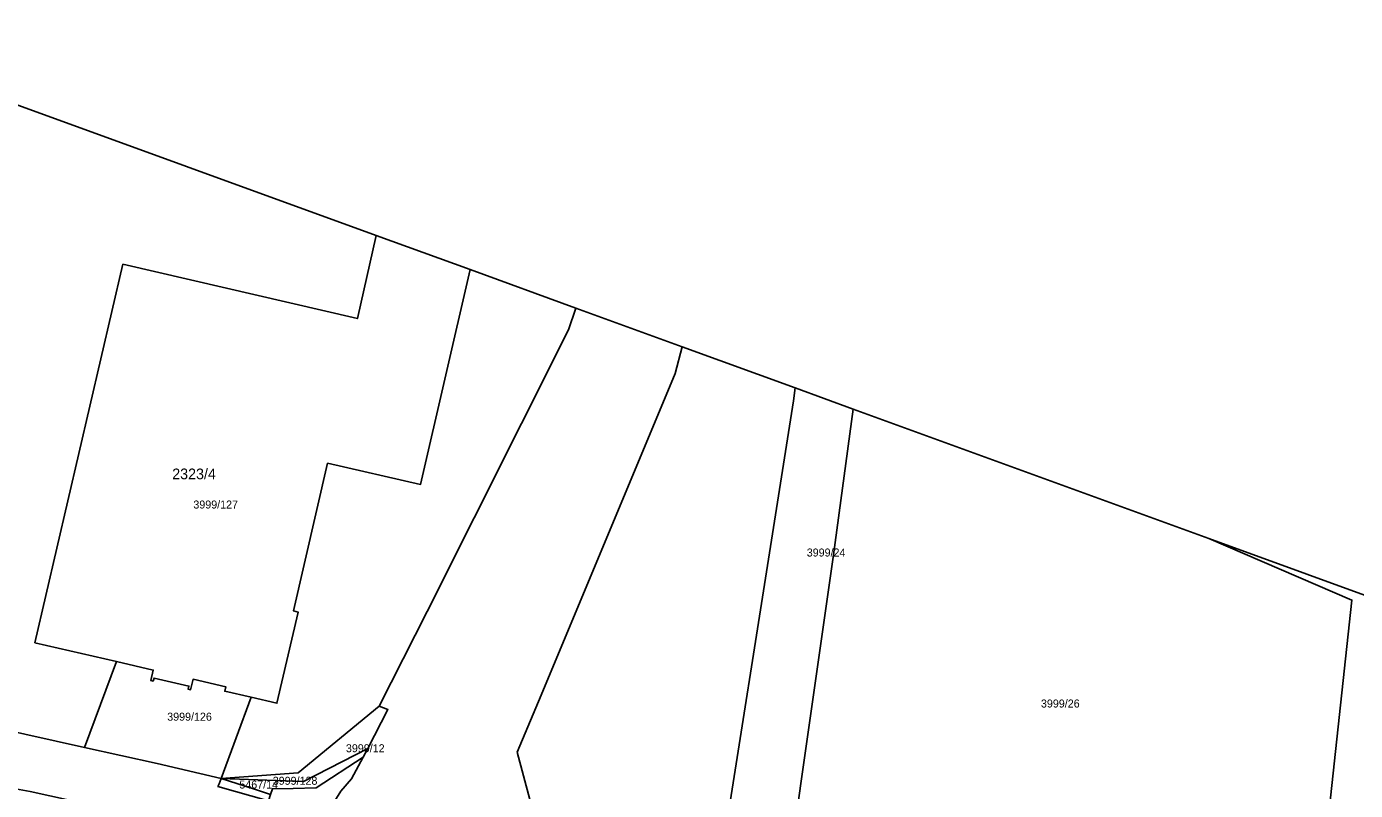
# Model space of a CAD drawing. Extents: x -570104 to -569328, y -1087857 to -1087418.
# Drawn here: x -569780.6 to -569531.5, y -1087571.3 to -1087428.2 of the extents above; entities that cross this region are included whole.
import ezdxf

# ---------------------------------------------------------------- set-up
doc = ezdxf.new("R2010")
doc.units = 0
for name, color, linetype in [('Adresní místo-text', 7, 'Continuous'), ('Parcela-polygon', 7, 'Continuous'), ('Parcela-text', 7, 'Continuous')]:
    doc.layers.add(name, color=color, linetype=linetype)

msp = doc.modelspace()

# ---------------------------------------------------------------- linework, layer by layer
at = {"layer": 'Parcela-polygon'}
for p, q in [((-569715.03, -1087467.34), (-569822.61, -1087428.2)), ((-569697.44, -1087473.74), (-569715.03, -1087467.34)), ((-569677.61, -1087480.95), (-569697.44, -1087473.74)), ((-569657.69, -1087488.2), (-569677.61, -1087480.95)), ((-569636.55, -1087495.89), (-569657.69, -1087488.2)), ((-569625.65, -1087499.86), (-569636.55, -1087495.89)), ((-569559, -1087524.1), (-569625.65, -1087499.86))]:
    msp.add_line(p, q, dxfattribs=at)
for points in [[(-569822.61, -1087428.2), (-569822.82, -1087428.95), (-569824.63, -1087435.4), (-569829.67, -1087453.35), (-569845.61, -1087508.96), (-569852.89, -1087536.4), (-569837.58, -1087552.32), (-569829.74, -1087553.51), (-569813.25, -1087555.99), (-569786.28, -1087559.57), (-569769.73, -1087563.25), (-569763.69, -1087547.17), (-569779, -1087543.64), (-569762.52, -1087472.72), (-569718.57, -1087482.91), (-569715.03, -1087467.34)], [(-569715.03, -1087467.34), (-569718.57, -1087482.91), (-569762.52, -1087472.72), (-569779, -1087543.64), (-569763.69, -1087547.17), (-569756.82, -1087548.76), (-569757.27, -1087550.72), (-569756.86, -1087550.83), (-569756.68, -1087550.26), (-569750.14, -1087551.74), (-569750.26, -1087552.35), (-569749.82, -1087552.43), (-569749.36, -1087550.47), (-569743.24, -1087551.87), (-569743.42, -1087552.72), (-569738.49, -1087553.86), (-569733.65, -1087554.97), (-569729.68, -1087537.88), (-569730.53, -1087537.68), (-569724.17, -1087510.02), (-569706.74, -1087513.97), (-569697.44, -1087473.74)], [(-569697.44, -1087473.74), (-569706.74, -1087513.97), (-569724.17, -1087510.02), (-569730.53, -1087537.68), (-569729.68, -1087537.88), (-569733.65, -1087554.97), (-569738.49, -1087553.86), (-569744.09, -1087569.05), (-569729.67, -1087568), (-569714.5, -1087555.5), (-569705.5, -1087537.75), (-569679, -1087485), (-569677.61, -1087480.95)], [(-569677.61, -1087480.95), (-569679, -1087485), (-569705.5, -1087537.75), (-569714.5, -1087555.5), (-569712.84, -1087556.16), (-569716.64, -1087563.44), (-569717.5, -1087565.1), (-569719.66, -1087569.11), (-569721.65, -1087571.42)], [(-569657.69, -1087488.2), (-569659, -1087493.2), (-569684.16, -1087553.44), (-569688.63, -1087564.12), (-569686.23, -1087572.99), (-569680.91, -1087587.07), (-569672.82, -1087596.37), (-569655.79, -1087606.73), (-569655.45, -1087604.65), (-569653.75, -1087605.49), (-569636.87, -1087498.32), (-569636.55, -1087495.89)], [(-569686.23, -1087572.99), (-569688.63, -1087564.12), (-569684.16, -1087553.44), (-569659, -1087493.2), (-569657.69, -1087488.2)], [(-569636.55, -1087495.89), (-569636.87, -1087498.32), (-569653.75, -1087605.49), (-569643.58, -1087610.64), (-569644.05, -1087613.5), (-569641.87, -1087614.64), (-569629.33, -1087527.19), (-569625.65, -1087499.86)], [(-569625.65, -1087499.86), (-569629.33, -1087527.19), (-569641.87, -1087614.64), (-569603.81, -1087634.48), (-569594.58, -1087639.86), (-569591.97, -1087641.18), (-569576.77, -1087648.59), (-569546.02, -1087663.53), (-569532.21, -1087535.63), (-569559, -1087524.1)], [(-569361.55, -1087675.44), (-569410.01, -1087578.31), (-569559, -1087524.1)], [(-569559, -1087524.1), (-569532.21, -1087535.63), (-569546.02, -1087663.53), (-569540.95, -1087665.98), (-569531.99, -1087590.85), (-569361.55, -1087675.44)], [(-569791.66, -1087569.4), (-569779.9, -1087571.5), (-569769.4, -1087573.82), (-569762.46, -1087575.23), (-569750.15, -1087578.73), (-569734.75, -1087583.54), (-569731.39, -1087584.88), (-569734.42, -1087583.23), (-569737.96, -1087582.13), (-569735.2, -1087573.26), (-569744.7, -1087570.56), (-569744.5, -1087570.07), (-569744.09, -1087569.05), (-569756.08, -1087566.28), (-569769.73, -1087563.25), (-569786.28, -1087559.57)]]:
    msp.add_lwpolyline(points, dxfattribs=at)
for points in [[(-569738.49, -1087553.86), (-569743.42, -1087552.72), (-569743.24, -1087551.87), (-569749.36, -1087550.47), (-569749.82, -1087552.43), (-569750.26, -1087552.35), (-569750.14, -1087551.74), (-569756.68, -1087550.26), (-569756.86, -1087550.83), (-569757.27, -1087550.72), (-569756.82, -1087548.76), (-569763.69, -1087547.17), (-569769.73, -1087563.25), (-569756.08, -1087566.28), (-569744.09, -1087569.05)], [(-569729.67, -1087568), (-569744.09, -1087569.05), (-569728.64, -1087569.65), (-569716.64, -1087563.44), (-569712.84, -1087556.16), (-569714.5, -1087555.5)], [(-569726.3, -1087570.8), (-569717.5, -1087565.1), (-569716.64, -1087563.44), (-569728.64, -1087569.65), (-569744.09, -1087569.05), (-569738.01, -1087571.03), (-569734.83, -1087572.06), (-569734.5, -1087571), (-569730.61, -1087570.91)], [(-569717.5, -1087565.1), (-569726.3, -1087570.8), (-569730.61, -1087570.91), (-569734.5, -1087571), (-569734.83, -1087572.06), (-569735.2, -1087573.26), (-569737.96, -1087582.13), (-569734.42, -1087583.23), (-569731.39, -1087584.88), (-569728.33, -1087586.54), (-569725.74, -1087589.24), (-569725.45, -1087589.78), (-569726.18, -1087583.85), (-569726.04, -1087581.55), (-569725.64, -1087580.08), (-569725.19, -1087578.13), (-569724.57, -1087576.07), (-569721.65, -1087571.42), (-569719.66, -1087569.11)], [(-569744.09, -1087569.05), (-569744.5, -1087570.07), (-569744.7, -1087570.56), (-569735.2, -1087573.26), (-569734.83, -1087572.06), (-569738.01, -1087571.03)]]:
    msp.add_lwpolyline(points, close=True, dxfattribs=at)

# ---------------------------------------------------------------- texts
at = {"layer": 'Adresní místo-text'}
msp.add_text('2323/4', height=2, dxfattribs=at).set_placement((-569753.27, -1087513))
at = {"layer": 'Parcela-text'}
for s, p in [('3999/127', (-569749.31, -1087518.49)), ('3999/24', (-569634.36, -1087527.48)), ('3999/26', (-569590.47, -1087555.77)), ('3999/126', (-569754.21, -1087558.24)), ('3999/12', (-569720.72, -1087564.15)), ('5467/14', (-569740.69, -1087570.95)), ('3999/128', (-569734.43, -1087570.24))]:
    msp.add_text(s, height=1.5, dxfattribs=at).set_placement(p)

doc.saveas('drawing.dxf')
